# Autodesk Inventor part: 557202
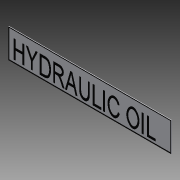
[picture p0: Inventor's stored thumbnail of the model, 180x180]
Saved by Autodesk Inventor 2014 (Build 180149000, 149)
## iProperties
Shininess: 20.0
Length Units: 11272
Angle Units: 11279
Time Units: 11290
Mass Units: 11286
Length Display Precision: 3
Angle Display Precision: 2
Company: Autodesk, Inc.
Created: 2002-08
Part Number: 557202
Material: Generic
Description: DECAL;A; HYDRAULIC OIL
Document SubType Name: Modeling
Designer: Autodesk, Inc.
Density: 1 g/cm^3
Mass: 1.11211 g
Surface Area: 76.184 cm^2
Volume: 1.11211 cm^3
Appearance: White (Flat)
Density: 0.0
Volumn: 0.0
Area: 0.0
PropertySet Name: Model Information
Control State: 0
Master: False
Checked Out: False
Last Check In By: JT
Last Check In Date: 2003-06-20
Title: DECAL;A; HYDRAULIC OIL
Author: Autodesk, Inc.
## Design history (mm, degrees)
sketch "Sketch1"
  geometry: L1 (0, 0)-(141.287, 0); L2 (141.287, 0)-(141.288, 25.4); L3 (141.288, 25.4)-(0, 25.4); L4 (0, 25.4)-(0, 0)
  constraints: 8 end point, 2 parallel, 1 horizontal, 1 perpendicular
  dimensions: "d3" = 141.2875 distance of L1.start L1.end; "d4" = 25.4 distance of L3.end L1.start
extrude "Extrusion2" new body sketch "Sketch1" distance "d5" = 0.254; taper "d6" = 0 deg
sketch "Sketch2"
  geometry: L1 (0, 0)-(0, 25.4) reference; L2 (141.287, 0)-(0, 0) reference; L3 (0, 25.4)-(141.288, 25.4) reference; L4 (0, 2.665)-(3.315, 2.665); L5 (4.696, 2.665)-(4.696, 18.54); L6 (4.696, 18.54)-(6.076, 18.54); L7 (6.076, 18.54)-(6.076, 12.098); L8 (6.076, 12.098)-(12.288, 12.098); L9 (12.288, 12.098)-(12.288, 18.54); L10 (12.288, 18.54)-(13.669, 18.54); L11 (13.669, 18.54)-(13.669, 2.665); L12 (13.669, 2.665)-(12.288, 2.665); L13 (12.288, 2.665)-(12.288, 10.258); L14 (12.288, 10.258)-(6.076, 10.258); L15 (6.076, 10.258)-(6.076, 2.665); L16 (6.076, 2.665)-(4.696, 2.665); L17 (19.651, 2.665)-(19.651, 9.391); L18 (19.651, 9.391)-(15.279, 18.54); L19 (15.279, 18.54)-(16.933, 18.54); L20 (16.933, 18.54)-(19.241, 13.716); L21 (21.66, 13.827)-(23.749, 18.54); L22 (23.749, 18.54)-(25.402, 18.54); L23 (25.402, 18.54)-(21.031, 9.391); L24 (21.031, 9.391)-(21.031, 2.665); L25 (21.031, 2.665)-(19.651, 2.665); L26 (27.243, 2.665)-(27.243, 18.54); L27 (27.243, 18.54)-(31.269, 18.54); L28 (31.46, 2.665)-(27.243, 2.665); L29 (28.623, 4.506)-(31.266, 4.506); L30 (31.222, 16.7)-(28.623, 16.7); L31 (28.623, 16.7)-(28.623, 4.506); L32 (38.977, 2.665)-(38.977, 18.54); L33 (38.977, 18.54)-(43.898, 18.54); L34 (46.673, 7.069)-(48.607, 2.665); L35 (48.607, 2.665)-(46.986, 2.665); L36 (46.986, 2.665)-(45.48, 6.03); L37 (42.104, 9.798)-(40.357, 9.798); L38 (40.357, 9.798)-(40.357, 2.665); L39 (40.357, 2.665)-(38.977, 2.665); L40 (40.357, 11.638)-(43.596, 11.638); L41 (43.959, 16.7)-(40.357, 16.7); L42 (40.357, 16.7)-(40.357, 11.638); L43 (49.236, 2.665)-(53.77, 18.54); L44 (53.77, 18.54)-(55.243, 18.54); L45 (55.243, 18.54)-(59.777, 2.665); L46 (59.777, 2.665)-(58.303, 2.665); L47 (58.303, 2.665)-(56.994, 7.497); L48 (56.994, 7.497)-(52.019, 7.497); L49 (52.019, 7.497)-(50.71, 2.665); L50 (50.71, 2.665)-(49.236, 2.665); L51 (52.515, 9.337)-(56.498, 9.337); L52 (56.498, 9.337)-(55.359, 13.543); L53 (53.734, 13.842)-(52.515, 9.337); L54 (69.116, 18.54)-(70.497, 18.54); L55 (70.497, 18.54)-(70.497, 9.391); L56 (61.524, 9.391)-(61.524, 18.54); L57 (61.524, 18.54)-(62.904, 18.54); L58 (62.904, 18.54)-(62.904, 9.517); L59 (69.116, 9.517)-(69.116, 18.54); L60 (73.257, 2.665)-(73.257, 18.54); L61 (73.257, 18.54)-(74.638, 18.54); L62 (74.638, 18.54)-(74.638, 4.506); L63 (74.638, 4.506)-(80.39, 4.506); L64 (80.39, 4.506)-(80.39, 2.665)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; 116 further points
  constraints: 164 end point, 3 parallel, 2 perpendicular, 1 point on line, 167 other
  dimensions: "d7" = 0.762 distance between parallel lines of L2 L83; "d8" = 0.762 distance between parallel lines of L1 L82; "d9" = 0.762 distance between parallel lines of L3 L85; "d10" = 0.8128 distance between parallel lines of L86 L84
extrude "Extrusion3" join sketch "Sketch2" distance "d11" = 0.254; taper "d12" = 0 deg
body "Solid1"
